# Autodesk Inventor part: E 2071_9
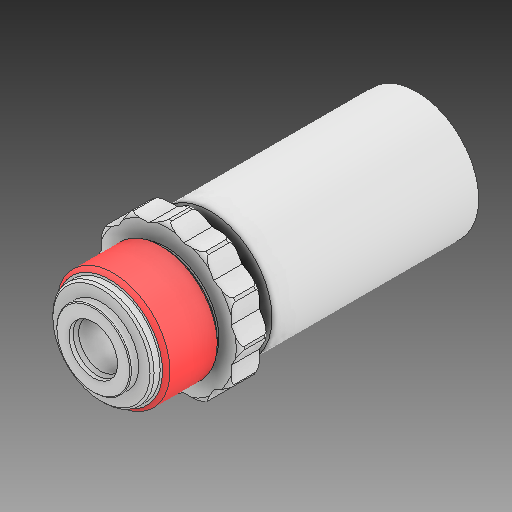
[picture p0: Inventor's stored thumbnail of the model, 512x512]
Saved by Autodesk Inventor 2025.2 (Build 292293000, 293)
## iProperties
Created: 2025-04
Part Number: E 2071_9
Material: Všeobecné
Document SubType Name: Modeling
Designer: Patrik
Density: 1 g/cm^3
Appearance: Výchozí
Mass: 45.3548 g
Surface Area: 131.024 cm^2
Volume: 45.3548 cm^3
Author: Patrik
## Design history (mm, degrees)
feature "Base1"
node "Těleso1"
